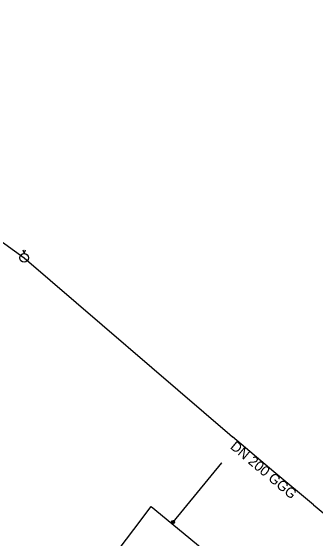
# Model space of a CAD drawing. Extents: x -482851 to -482354, y -1127969 to -1127406.
# Drawn here: x -482698.8 to -482650.2, y -1127555.4 to -1127471.2 of the extents above; entities that cross this region are included whole.
import ezdxf

# ---------------------------------------------------------------- set-up
doc = ezdxf.new("R2010")
doc.units = 0
for name, color, linetype in [('_hydrantova_odbocka_', 7, 'Continuous'), ('_voda_smvak_prevzato_z_dokumentace_', 7, 'Continuous'), ('Default', 7, 'Continuous'), ('MoLevel 27', 7, 'Continuous'), ('MoLevel 30', 7, 'Continuous'), ('MoLevel 46', 7, 'Continuous')]:
    doc.layers.add(name, color=color, linetype=linetype)

# ---------------------------------------------------------------- blocks, each defined once
blk = doc.blocks.new('_uzaver_')
at = {"layer": 'Default'}
for p, q in [((-0.000035, -0.000035), (0.000035, 0.000035)), ((0.000035, -0.000035), (-0.000035, 0.000035))]:
    blk.add_line(p, q, dxfattribs=at)
for radius in [0.00005, 0.0000025]:
    blk.add_circle((0, 0), radius, dxfattribs=at)
blk = doc.blocks.new('_sachta_voda_')
at = {"layer": 'Default'}
blk.add_lwpolyline([(-0.00001, 0.000065), (0, 0.000035), (0.00001, 0.000065)], dxfattribs=at)
blk.add_circle((0, 0), 0.000035, dxfattribs=at)

msp = doc.modelspace()

# ---------------------------------------------------------------- linework, layer by layer
at = {"layer": '_hydrantova_odbocka_'}
msp.add_line((-482673.119, -1127552.991), (-482672.928, -1127552.759), dxfattribs=at)
msp.add_lwpolyline([(-482672.928, -1127552.758), (-482665.142, -1127543.296), (-482665.142, -1127543.296)], dxfattribs=at)
at = {"layer": '_voda_smvak_prevzato_z_dokumentace_'}
for points in [[(-482751.265, -1127471.248), (-482747.73, -1127473.714), (-482696.674, -1127510.662)], [(-482696.674, -1127510.662), (-482663.89, -1127538.82), (-482663.43, -1127539.2)], [(-482650.53, -1127550), (-482656.89, -1127544.73), (-482663.43, -1127539.2)], [(-482694.945, -1127603.596), (-482694.232, -1127599.185), (-482691.973, -1127583.921), (-482689.559, -1127567.61), (-482679.183, -1127553.955), (-482676.4, -1127550.292), (-482673.119, -1127552.991), (-482664.934, -1127559.726), (-482657.295, -1127565.933), (-482656.661, -1127566.463), (-482626.436, -1127591.744), (-482622.922, -1127594.632), (-482595.905, -1127616.837), (-482593.02, -1127620.913), (-482592.524, -1127621.613), (-482587.023, -1127630.022), (-482572.112, -1127649.751), (-482571.274, -1127650.874), (-482568.881, -1127654.082), (-482563.796, -1127660.897)], [(-482650.53, -1127550), (-482649.94, -1127550.49), (-482644.562, -1127554.99), (-482616.216, -1127578.536), (-482587.416, -1127604.56), (-482576.326, -1127616.559), (-482572.3, -1127621.68), (-482572.04, -1127621.97)]]:
    msp.add_lwpolyline(points, dxfattribs=at)

# ---------------------------------------------------------------- block references
at = {"layer": 'MoLevel 27', "xscale": 5000, "yscale": 5000, "rotation": 50.5530166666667}
msp.add_blockref('_uzaver_', (-482672.928, -1127552.758), dxfattribs=at)
at = {"layer": 'MoLevel 30', "xscale": 20000, "yscale": 20000}
msp.add_blockref('_sachta_voda_', (-482696.674, -1127510.662), dxfattribs=at)

# ---------------------------------------------------------------- texts
at = {"layer": 'MoLevel 46'}
msp.add_text('DN 200 GGG', height=1.6049, rotation=320.0688, dxfattribs=at).set_placement((-482663.927, -1127540.933))

doc.saveas('drawing.dxf')
